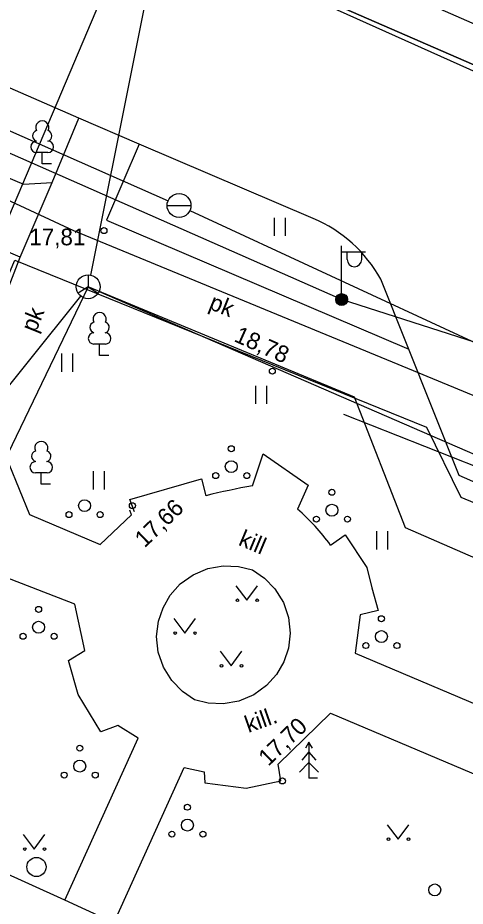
# Model space of a CAD drawing. Extents: x 713497 to 713863, y 6590062 to 6590327.
# Drawn here: x 713569.52 to 713588.22, y 6590222.86 to 6590260.04 of the extents above; entities that cross this region are included whole.
import ezdxf

# ---------------------------------------------------------------- set-up
doc = ezdxf.new("R2010")
doc.units = 0
for name, color, linetype in [('HALJASTUS', 7, 'Continuous'), ('HOONE', 7, 'Continuous'), ('KORGUS', 7, 'Continuous'), ('KPKAABEL', 7, 'Continuous'), ('MPKAABEL', 7, 'Continuous'), ('POST', 7, 'Continuous'), ('PUU', 7, 'Continuous'), ('SIKAEV', 7, 'Continuous'), ('SITRASS', 7, 'Continuous'), ('SKTRASS', 7, 'Continuous'), ('TEE', 7, 'Continuous'), ('VKAEV', 7, 'Continuous'), ('VTRASS', 7, 'Continuous'), ('По умолчанию', 7, 'Continuous'), ('Слой 1', 7, 'Continuous')]:
    doc.layers.add(name, color=color, linetype=linetype)

msp = doc.modelspace()

# ---------------------------------------------------------------- linework, layer by layer
at = {"layer": 'HALJASTUS'}
for p, q in [((713580.236, 6590251.671), (713580.236, 6590250.91)), ((713580.692, 6590251.671), (713580.692, 6590250.91)), ((713571.349, 6590245.984), (713571.349, 6590245.223)), ((713571.804, 6590245.984), (713571.804, 6590245.223)), ((713579.456, 6590244.638), (713579.456, 6590243.877)), ((713579.911, 6590244.638), (713579.911, 6590243.877)), ((713572.673, 6590241.063), (713572.673, 6590240.301)), ((713573.128, 6590241.063), (713573.128, 6590240.301)), ((713584.52, 6590238.547), (713584.52, 6590237.786)), ((713584.975, 6590238.547), (713584.975, 6590237.786)), ((713578.637, 6590236.267), (713579.1, 6590235.66)), ((713579.1, 6590235.66), (713579.546, 6590236.267)), ((713576.037, 6590234.897), (713576.5, 6590234.29)), ((713576.5, 6590234.29), (713576.946, 6590234.897)), ((713577.977, 6590233.527), (713578.44, 6590232.92)), ((713578.44, 6590232.92), (713578.886, 6590233.527)), ((713584.957, 6590226.267), (713585.42, 6590225.66)), ((713585.42, 6590225.66), (713585.866, 6590226.267)), ((713569.747, 6590225.857), (713570.21, 6590225.25)), ((713570.21, 6590225.25), (713570.656, 6590225.857))]:
    msp.add_line(p, q, dxfattribs=at)
for centre, radius in [((713578.444, 6590242.003), 0.125), ((713578.444, 6590241.253), 0.25), ((713577.794, 6590240.878), 0.125), ((713579.094, 6590240.878), 0.125), ((713582.65, 6590240.181), 0.125), ((713582.65, 6590239.431), 0.25), ((713582, 6590239.056), 0.125), ((713583.3, 6590239.056), 0.125), ((713578.699, 6590235.66), 0.055), ((713579.528, 6590235.66), 0.055), ((713570.39, 6590235.28), 0.125), ((713570.39, 6590234.53), 0.25), ((713584.72, 6590234.89), 0.125), ((713584.72, 6590234.14), 0.25), ((713569.74, 6590234.155), 0.125), ((713571.04, 6590234.155), 0.125), ((713576.099, 6590234.29), 0.055), ((713576.928, 6590234.29), 0.055), ((713584.07, 6590233.765), 0.125), ((713585.37, 6590233.765), 0.125), ((713578.039, 6590232.92), 0.055), ((713578.868, 6590232.92), 0.055), ((713572.11, 6590229.47), 0.125), ((713572.11, 6590228.72), 0.25), ((713571.46, 6590228.345), 0.125), ((713572.76, 6590228.345), 0.125), ((713576.61, 6590227), 0.125), ((713576.61, 6590226.25), 0.25), ((713575.96, 6590225.875), 0.125), ((713577.26, 6590225.875), 0.125), ((713585.019, 6590225.66), 0.055), ((713585.848, 6590225.66), 0.055), ((713569.809, 6590225.25), 0.055), ((713570.638, 6590225.25), 0.055), ((713570.3, 6590224.5), 0.4)]:
    msp.add_circle(centre, radius, dxfattribs=at)
at = {"layer": 'HOONE'}
msp.add_lwpolyline([(713527.261, 6590284.603), (713571.838, 6590266.115), (713573.888, 6590266.247), (713614.395, 6590248.483), (713630.517, 6590241.151), (713667.174, 6590224.027), (713666.91, 6590213.67), (713710.13, 6590192.26), (713734.713, 6590179.152)], dxfattribs=at)
at = {"layer": 'KORGUS'}
for centre in [(713573.12, 6590251.13), (713580.16, 6590245.25), (713574.31, 6590239.62), (713580.58, 6590228.1)]:
    msp.add_circle(centre, 0.125, dxfattribs=at)
at = {"layer": 'KPKAABEL'}
msp.add_lwpolyline([(713529.988, 6590287.362), (713528.13, 6590283.39), (713562.908, 6590269.342), (713609.57, 6590248.393), (713642.834, 6590233.164), (713665.543, 6590222.669), (713703.801, 6590203.145), (713710.007, 6590200.019), (713735.256, 6590187.298), (713757.247, 6590176.218), (713786.95, 6590160.25), (713778.485, 6590144.103)], dxfattribs=at)
at = {"layer": 'MPKAABEL'}
msp.add_lwpolyline([(713649.332, 6590187.338), (713640.094, 6590185.585), (713635.77, 6590206.95), (713632.04, 6590224.25), (713630.57, 6590226.81), (713628.65, 6590228.67), (713627.42, 6590229.49), (713598.73, 6590243.21), (713583.058, 6590248.245), (713565.046, 6590256.189), (713523.612, 6590274.149), (713521.905, 6590274.877)], dxfattribs=at)
at = {"layer": 'POST'}
for p, q in [((713583.058, 6590248.495), (713583.058, 6590250.495)), ((713583.058, 6590250.245), (713584.058, 6590250.245)), ((713583.285, 6590249.924), (713583.285, 6590250.245)), ((713583.898, 6590249.924), (713583.898, 6590250.245))]:
    msp.add_line(p, q, dxfattribs=at)
for centre, radius in [((713583.058, 6590248.245), 0.25), ((713583.058, 6590248.245), 0.225), ((713583.058, 6590248.245), 0.2), ((713583.058, 6590248.245), 0.175), ((713583.058, 6590248.245), 0.15), ((713583.058, 6590248.245), 0.125), ((713583.058, 6590248.245), 0.1), ((713583.058, 6590248.245), 0.075), ((713583.058, 6590248.245), 0.05), ((713583.058, 6590248.245), 0.025), ((713586.95, 6590223.54), 0.25)]:
    msp.add_circle(centre, radius, dxfattribs=at)
msp.add_arc((713583.591, 6590249.924), 0.306, 180, 0, dxfattribs=at)
at = {"layer": 'PUU'}
for p, q in [((713570.782, 6590254.397), (713570.302, 6590254.397)), ((713570.542, 6590253.922), (713570.542, 6590254.397)), ((713570.922, 6590253.922), (713570.542, 6590253.922)), ((713573.18, 6590246.381), (713572.7, 6590246.381)), ((713572.94, 6590245.906), (713572.94, 6590246.381)), ((713573.32, 6590245.906), (713572.94, 6590245.906)), ((713570.742, 6590240.988), (713570.262, 6590240.988)), ((713570.502, 6590240.513), (713570.502, 6590240.988)), ((713570.882, 6590240.513), (713570.502, 6590240.513)), ((713581.69, 6590229.72), (713581.54, 6590229.47)), ((713581.84, 6590229.47), (713581.69, 6590229.72)), ((713581.69, 6590229.72), (713581.69, 6590228.22)), ((713581.69, 6590229.32), (713581.39, 6590228.97)), ((713581.99, 6590228.97), (713581.69, 6590229.32)), ((713581.69, 6590228.87), (713581.29, 6590228.47)), ((713582.09, 6590228.47), (713581.69, 6590228.87)), ((713582.05, 6590228.22), (713581.69, 6590228.22))]:
    msp.add_line(p, q, dxfattribs=at)
for centre, radius, start, end in [((713570.542, 6590255.442), 0.277, 332.5799, 207.4201), ((713570.372, 6590255.094), 0.233, 109.0217, 253.1415), ((713570.712, 6590255.094), 0.233, 286.8508, 70.9859), ((713570.304, 6590254.634), 0.238, 90.0016, 269.3953), ((713570.779, 6590254.634), 0.238, 270.6047, 89.9984), ((713572.94, 6590247.426), 0.277, 332.5799, 207.4201), ((713572.77, 6590247.078), 0.233, 109.0217, 253.1415), ((713573.11, 6590247.078), 0.233, 286.8508, 70.9859), ((713572.703, 6590246.618), 0.238, 90.0016, 269.3953), ((713573.178, 6590246.618), 0.238, 270.6047, 89.9984), ((713570.502, 6590242.033), 0.277, 332.5799, 207.4201), ((713570.332, 6590241.686), 0.233, 109.0217, 253.1415), ((713570.672, 6590241.686), 0.233, 286.8508, 70.9859), ((713570.264, 6590241.226), 0.238, 90.0016, 269.3953), ((713570.739, 6590241.226), 0.238, 270.6047, 89.9984)]:
    msp.add_arc(centre, radius, start, end, dxfattribs=at)
at = {"layer": 'SIKAEV'}
for p, q in [((713572.461, 6590249.281), (713572.461, 6590248.781)), ((713572.461, 6590248.781), (713572.046, 6590248.506)), ((713572.461, 6590248.781), (713572.876, 6590248.506))]:
    msp.add_line(p, q, dxfattribs=at)
msp.add_circle((713572.461, 6590248.781), 0.5, dxfattribs=at)
at = {"layer": 'SITRASS'}
for points in [[(713566.805, 6590246.216), (713573.691, 6590262.451), (713576.214, 6590265.257), (713576.368, 6590265.991), (713576.338, 6590266.741)], [(713576.062, 6590266.76), (713572.56, 6590249.272)], [(713572.92, 6590248.582), (713604.002, 6590235.074)], [(713567.593, 6590242.705), (713572.149, 6590248.391)]]:
    msp.add_lwpolyline(points, dxfattribs=at)
at = {"layer": 'SKTRASS'}
msp.add_lwpolyline([(713588.792, 6590241.201), (713583.155, 6590243.435)], dxfattribs=at)
at = {"layer": 'TEE'}
for points in [[(713666.108, 6590223.285), (713665.125, 6590223.708), (713665.399, 6590224.292), (713664.368, 6590224.758), (713664.105, 6590224.17), (713638.24, 6590236.433), (713616.511, 6590245.926), (713594.802, 6590255.36), (713577.886, 6590262.747), (713575.141, 6590263.944), (713556.827, 6590271.855), (713531.631, 6590282.846), (713531.578, 6590282.869)], [(713531.578, 6590282.869), (713531.631, 6590282.846), (713556.827, 6590271.855), (713575.141, 6590263.944), (713577.886, 6590262.747), (713594.802, 6590255.36), (713616.511, 6590245.926), (713638.24, 6590236.433), (713664.105, 6590224.17), (713664.368, 6590224.758), (713665.399, 6590224.292), (713665.125, 6590223.708), (713666.108, 6590223.285), (713666.434, 6590223.151), (713669.603, 6590225.318), (713669.834, 6590225.893), (713641.724, 6590238.195), (713621.946, 6590246.858), (713579.058, 6590265.436), (713577.886, 6590262.747)], [(713567.967, 6590245.728), (713569.621, 6590250.018), (713551.587, 6590257.762), (713546.285, 6590260.188)], [(713554.92, 6590259.35), (713569.762, 6590253.078), (713570.953, 6590253.138), (713572.077, 6590255.831)], [(713581.873, 6590251.637), (713574.594, 6590254.75), (713572.077, 6590255.831), (713569.207, 6590257.092)], [(713574.594, 6590254.75), (713573.23, 6590251.57), (713585.866, 6590246.162)], [(713569.621, 6590250.018), (713570.953, 6590253.138)], [(713630.83, 6590222.031), (713616.226, 6590228.479), (713587.97, 6590240.88), (713584.698, 6590249.092)], [(713628.097, 6590220.194), (713623.489, 6590222.15), (713622.094, 6590222.702), (713604.901, 6590230.317), (713585.723, 6590238.689), (713583.599, 6590244.155), (713572.461, 6590248.781), (713569.103, 6590241.79)], [(713579.336, 6590240.451), (713579.783, 6590241.785), (713581.66, 6590240.481), (713581.21, 6590239.476)], [(713569.146, 6590241.376), (713570.004, 6590239.247), (713572.959, 6590237.996), (713574.268, 6590239.239), (713574.21, 6590239.427)], [(713574.397, 6590239.367), (713574.21, 6590239.875), (713577.194, 6590240.748), (713577.385, 6590240.038)], [(713582.593, 6590237.969), (713583.205, 6590238.402), (713584.11, 6590237.038), (713584.314, 6590236.18)], [(713576.9, 6590231.5), (713576.4, 6590231.84), (713575.96, 6590232.3), (713575.61, 6590232.86), (713575.39, 6590233.49), (713575.32, 6590234.15), (713575.4, 6590234.78), (713575.59, 6590235.35), (713575.89, 6590235.87), (713576.31, 6590236.35), (713576.85, 6590236.73), (713577.46, 6590236.99), (713578.11, 6590237.1), (713578.75, 6590237.08), (713579.33, 6590236.93)], [(713571.491, 6590223.115), (713574.552, 6590229.884), (713573.706, 6590230.421), (713572.985, 6590230.159), (713572.043, 6590231.724), (713571.643, 6590233.145), (713572.317, 6590233.557), (713571.906, 6590235.496), (713568.807, 6590236.699)], [(713579.33, 6590236.93), (713579.83, 6590236.59), (713580.27, 6590236.14), (713580.62, 6590235.57), (713580.83, 6590234.94), (713580.9, 6590234.29), (713580.83, 6590233.65), (713580.64, 6590233.08), (713580.34, 6590232.56), (713579.92, 6590232.09), (713579.38, 6590231.7), (713578.76, 6590231.44), (713578.11, 6590231.33), (713577.48, 6590231.36), (713576.9, 6590231.5)], [(713584.319, 6590236.178), (713584.579, 6590235.239), (713583.834, 6590235.055), (713583.62, 6590233.442), (713599.383, 6590226.769), (713600.647, 6590229.37)], [(713573.577, 6590222.248), (713576.477, 6590228.662), (713577.306, 6590228.488), (713577.342, 6590228.02), (713579.068, 6590227.804), (713580.515, 6590228.101), (713580.403, 6590228.806), (713582.597, 6590230.931), (713598.36, 6590224.258), (713596.683, 6590219.909)], [(713576.239, 6590220.92), (713571.491, 6590223.115), (713564.409, 6590226.32), (713563.5, 6590228.24)]]:
    msp.add_lwpolyline(points, dxfattribs=at)
for centre, radius, start, end in [((713579.56, 6590246.229), 5.883, 29.1316, 66.8484), ((713584.39, 6590211.772), 29.121, 99.9936, 103.9176), ((713575.255, 6590232.621), 9.08, 36.0878, 49.0215)]:
    msp.add_arc(centre, radius, start, end, dxfattribs=at)
at = {"layer": 'VKAEV'}
msp.add_line((713575.76, 6590252.18), (713576.76, 6590252.18), dxfattribs=at)
msp.add_circle((713576.26, 6590252.18), 0.5, dxfattribs=at)
at = {"layer": 'VTRASS'}
for points in [[(713632.54, 6590225.141), (713631.644, 6590225.667), (713613.144, 6590233.236), (713600.179, 6590239.452), (713599.949, 6590239.514), (713585.185, 6590245.627), (713571.869, 6590251.118), (713555.451, 6590258.762), (713536.955, 6590266.515), (713522.936, 6590272.405), (713508.982, 6590277.717), (713503.707, 6590280.197), (713496.861, 6590283.191)], [(713522.533, 6590275.945), (713575.803, 6590252.382)], [(713576.714, 6590251.97), (713600.281, 6590241.032)]]:
    msp.add_lwpolyline(points, dxfattribs=at)
at = {"layer": 'По умолчанию'}
for centre, radius in [((713572.31, 6590239.62), 0.25), ((713571.66, 6590239.245), 0.125), ((713572.96, 6590239.245), 0.125)]:
    msp.add_circle(centre, radius, dxfattribs=at)
at = {"layer": 'Слой 1'}
msp.add_lwpolyline([(713639.21, 6590161.17), (713619.31, 6590158.48), (713605.01, 6590158.14), (713587.01, 6590157.64), (713579.15, 6590161.09), (713575.14, 6590170.32), (713594.16, 6590210.61), (713559.07, 6590225.5), (713569.4, 6590249.89), (713586.61, 6590242.91), (713588.04, 6590239.97), (713627.31, 6590223.7), (713629.09, 6590219.58), (713632.13, 6590197.39)], close=True, dxfattribs=at)

# ---------------------------------------------------------------- texts
at = {"layer": 'KORGUS'}
msp.add_text('17,81', height=0.7, dxfattribs=at).set_placement((713570.002, 6590250.515))
for s, rotation, p in [('18,78', 335.9107, (713578.518, 6590246.514)), ('17,66', 43.9246, (713574.823, 6590237.83)), ('17,70', 43.9246, (713579.989, 6590228.686))]:
    msp.add_text(s, height=0.7, rotation=rotation, dxfattribs=at).set_placement(p)
at = {"layer": 'TEE'}
for s, rotation, p in [('pk', 338.0364, (713577.466, 6590247.867)), ('pk', 67.9381, (713570.273, 6590246.827)), ('kill', 337.2491, (713578.702, 6590237.984)), ('kill.', 19.4508, (713579.159, 6590230.106))]:
    msp.add_text(s, height=0.7, rotation=rotation, dxfattribs=at).set_placement(p)

doc.saveas('drawing.dxf')
